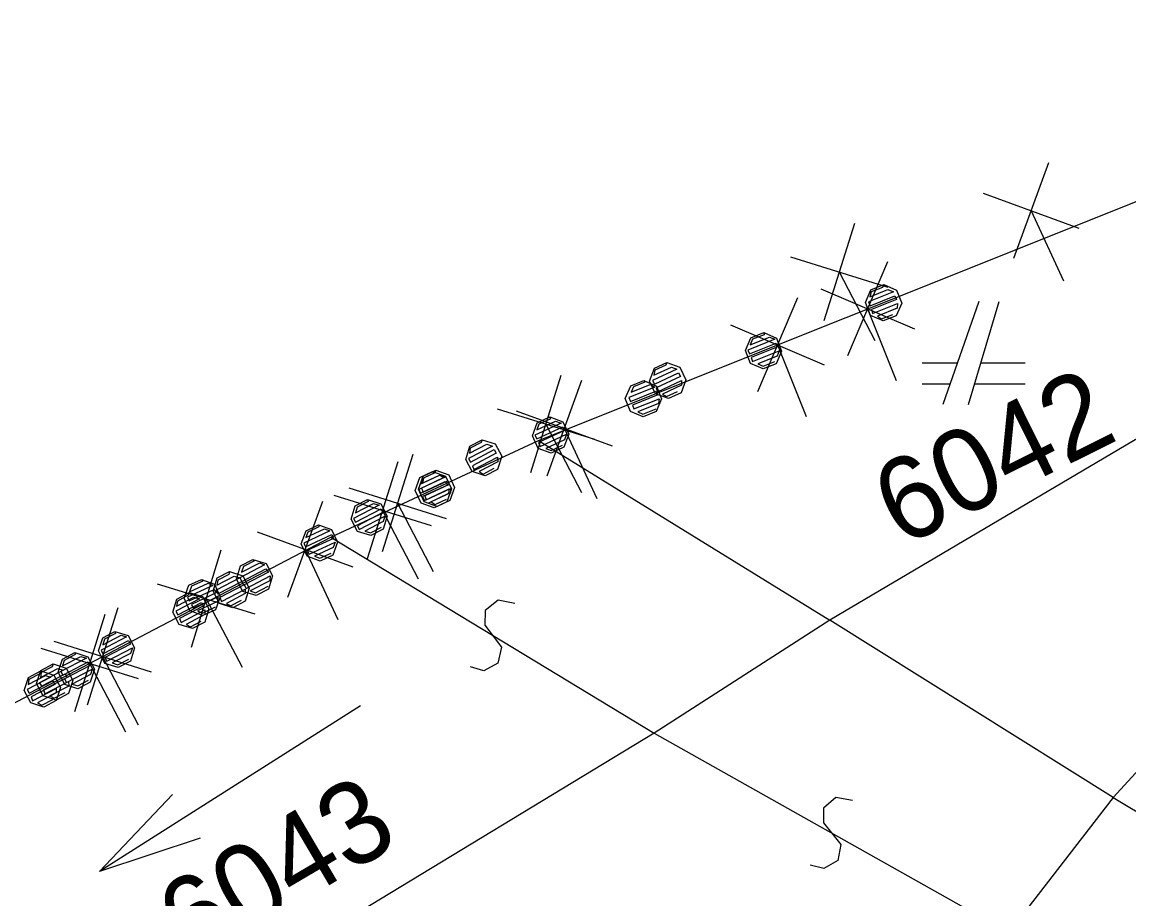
# Model space of a CAD drawing. Extents: x -266179 to -264727, y -1243225 to -1241702.
# Drawn here: x -265619.79 to -265598.3, y -1241752.17 to -1241735.15 of the extents above; entities that cross this region are included whole.
import ezdxf

# ---------------------------------------------------------------- set-up
doc = ezdxf.new("R2010")
doc.units = 0
for name, color, linetype in [('Vrstva 1', 7, 'Continuous'), ('Vrstva 19', 7, 'Continuous'), ('Vrstva 2', 7, 'Continuous'), ('Vrstva 21', 7, 'Continuous')]:
    doc.layers.add(name, color=color, linetype=linetype)

msp = doc.modelspace()

# ---------------------------------------------------------------- linework, layer by layer
at = {"layer": 'Vrstva 1'}
for p, q in [((-265609.77, -1241743.27), (-265589.45, -1241735.15)), ((-265585.26, -1241735.62), (-265604.11, -1241746.76)), ((-265585.26, -1241735.62), (-265598.61, -1241750.2)), ((-265601.22, -1241740.57), (-265601.92, -1241742.57)), ((-265601.42, -1241742.57), (-265600.82, -1241740.57)), ((-265601.64, -1241741.77), (-265602.32, -1241741.77)), ((-265600.32, -1241741.77), (-265601.18, -1241741.77)), ((-265602.32, -1241742.17), (-265601.78, -1241742.17)), ((-265601.3, -1241742.17), (-265600.32, -1241742.17)), ((-265613.8, -1241745.15), (-265609.77, -1241743.27)), ((-265609.77, -1241743.27), (-265604.11, -1241746.76)), ((-265617.23, -1241746.94), (-265613.8, -1241745.15)), ((-265604.11, -1241746.76), (-265607.52, -1241748.95)), ((-265598.61, -1241750.2), (-265604.11, -1241746.76)), ((-265622.91, -1241749.92), (-265617.23, -1241746.94)), ((-265613.227, -1241748.423), (-265618.293, -1241751.637)), ((-265607.52, -1241748.95), (-265618.34, -1241755.51)), ((-265598.61, -1241750.2), (-265600.64, -1241752.82)), ((-265598.61, -1241750.2), (-265594.43, -1241752.7))]:
    msp.add_line(p, q, dxfattribs=at)
msp.add_lwpolyline([(-265616.336, -1241750.988), (-265618.293, -1241751.637), (-265616.872, -1241750.144)], dxfattribs=at)
at = {"layer": 'Vrstva 19'}
for p, q in [((-265609.77, -1241743.27), (-265589.45, -1241735.15)), ((-265613.8, -1241745.15), (-265609.77, -1241743.27)), ((-265617.23, -1241746.94), (-265613.8, -1241745.15)), ((-265622.91, -1241749.92), (-265617.23, -1241746.94))]:
    msp.add_line(p, q, dxfattribs=at)
for points in [[(-265603.063, -1241740.246), (-265602.816, -1241740.352), (-265602.716, -1241740.603), (-265602.822, -1241740.849), (-265603.073, -1241740.95), (-265603.32, -1241740.844), (-265603.42, -1241740.593), (-265603.314, -1241740.346), (-265603.063, -1241740.246), (-265603.086, -1241740.298), (-265603.308, -1241740.387), (-265603.335, -1241740.483), (-265602.982, -1241740.342), (-265602.878, -1241740.387), (-265603.361, -1241740.58), (-265603.331, -1241740.654), (-265602.848, -1241740.461), (-265602.818, -1241740.536), (-265603.301, -1241740.729), (-265603.281, -1241740.807), (-265602.798, -1241740.614), (-265602.805, -1241740.703), (-265603.186, -1241740.855), (-265603.11, -1241740.911), (-265602.887, -1241740.822)], [(-265605.394, -1241741.177), (-265605.147, -1241741.283), (-265605.047, -1241741.534), (-265605.153, -1241741.78), (-265605.404, -1241741.881), (-265605.651, -1241741.775), (-265605.751, -1241741.524), (-265605.645, -1241741.277), (-265605.394, -1241741.177), (-265605.389, -1241741.218), (-265605.612, -1241741.307), (-265605.656, -1241741.411), (-265605.285, -1241741.262), (-265605.181, -1241741.307), (-265605.701, -1241741.515), (-265605.671, -1241741.589), (-265605.151, -1241741.381), (-265605.121, -1241741.456), (-265605.641, -1241741.663), (-265605.612, -1241741.738), (-265605.092, -1241741.53), (-265605.136, -1241741.634), (-265605.508, -1241741.782), (-265605.404, -1241741.827), (-265605.181, -1241741.738)], [(-265607.274, -1241741.754), (-265607.021, -1241741.846), (-265606.907, -1241742.091), (-265606.999, -1241742.343), (-265607.244, -1241742.457), (-265607.496, -1241742.365), (-265607.61, -1241742.12), (-265607.518, -1241741.868), (-265607.274, -1241741.754), (-265607.293, -1241741.807), (-265607.511, -1241741.908), (-265607.531, -1241742.006), (-265607.187, -1241741.846), (-265607.08, -1241741.884), (-265607.552, -1241742.104), (-265607.518, -1241742.177), (-265607.047, -1241741.957), (-265607.013, -1241742.029), (-265607.484, -1241742.249), (-265607.46, -1241742.326), (-265606.988, -1241742.106), (-265606.991, -1241742.196), (-265607.362, -1241742.369), (-265607.283, -1241742.42), (-265607.066, -1241742.319)], [(-265607.725, -1241742.108), (-265607.478, -1241742.214), (-265607.378, -1241742.465), (-265607.484, -1241742.711), (-265607.735, -1241742.812), (-265607.982, -1241742.706), (-265608.082, -1241742.455), (-265607.976, -1241742.208), (-265607.725, -1241742.108), (-265607.701, -1241742.141), (-265607.924, -1241742.23), (-265607.969, -1241742.334), (-265607.597, -1241742.186), (-265607.512, -1241742.238), (-265608.013, -1241742.438), (-265607.984, -1241742.513), (-265607.491, -1241742.316), (-265607.452, -1241742.387), (-265607.945, -1241742.583), (-265607.915, -1241742.657), (-265607.423, -1241742.461), (-265607.439, -1241742.554), (-265607.839, -1241742.713), (-265607.744, -1241742.761), (-265607.484, -1241742.658)], [(-265609.549, -1241742.814), (-265609.296, -1241742.906), (-265609.182, -1241743.151), (-265609.274, -1241743.403), (-265609.519, -1241743.517), (-265609.772, -1241743.425), (-265609.886, -1241743.18), (-265609.794, -1241742.928), (-265609.549, -1241742.814), (-265609.541, -1241742.854), (-265609.759, -1241742.956), (-265609.797, -1241743.062), (-265609.435, -1241742.893), (-265609.328, -1241742.932), (-265609.836, -1241743.168), (-265609.802, -1241743.241), (-265609.295, -1241743.004), (-265609.261, -1241743.077), (-265609.769, -1241743.313), (-265609.735, -1241743.386), (-265609.227, -1241743.149), (-265609.266, -1241743.256), (-265609.628, -1241743.425), (-265609.522, -1241743.463), (-265609.305, -1241743.362)], [(-265610.862, -1241743.256), (-265610.606, -1241743.336), (-265610.481, -1241743.576), (-265610.561, -1241743.832), (-265610.801, -1241743.957), (-265611.057, -1241743.876), (-265611.182, -1241743.637), (-265611.101, -1241743.381), (-265610.862, -1241743.256), (-265610.879, -1241743.31), (-265611.092, -1241743.421), (-265611.108, -1241743.519), (-265610.771, -1241743.344), (-265610.663, -1241743.378), (-265611.124, -1241743.618), (-265611.087, -1241743.689), (-265610.626, -1241743.448), (-265610.589, -1241743.519), (-265611.05, -1241743.76), (-265611.022, -1241743.836), (-265610.561, -1241743.595), (-265610.559, -1241743.684), (-265610.923, -1241743.874), (-265610.842, -1241743.922), (-265610.629, -1241743.811)], [(-265611.762, -1241743.848), (-265611.51, -1241743.94), (-265611.396, -1241744.185), (-265611.488, -1241744.437), (-265611.733, -1241744.551), (-265611.985, -1241744.459), (-265612.099, -1241744.214), (-265612.007, -1241743.962), (-265611.762, -1241743.848), (-265611.782, -1241743.901), (-265611.999, -1241744.002), (-265612.02, -1241744.1), (-265611.675, -1241743.94), (-265611.569, -1241743.978), (-265612.041, -1241744.198), (-265612.007, -1241744.271), (-265611.535, -1241744.051), (-265611.502, -1241744.123), (-265611.973, -1241744.343), (-265611.948, -1241744.42), (-265611.477, -1241744.2), (-265611.479, -1241744.29), (-265611.851, -1241744.463), (-265611.772, -1241744.514), (-265611.554, -1241744.413)], [(-265611.824, -1241743.874), (-265611.572, -1241743.966), (-265611.458, -1241744.211), (-265611.55, -1241744.463), (-265611.794, -1241744.577), (-265612.047, -1241744.485), (-265612.161, -1241744.24), (-265612.069, -1241743.988), (-265611.824, -1241743.874), (-265611.798, -1241743.906), (-265612.016, -1241744.007), (-265612.054, -1241744.114), (-265611.692, -1241743.945), (-265611.604, -1241743.992), (-265612.093, -1241744.22), (-265612.059, -1241744.292), (-265611.579, -1241744.069), (-265611.536, -1241744.137), (-265612.017, -1241744.361), (-265611.983, -1241744.433), (-265611.502, -1241744.209), (-265611.514, -1241744.303), (-265611.904, -1241744.485), (-265611.806, -1241744.528), (-265611.553, -1241744.409)], [(-265613.087, -1241744.417), (-265612.831, -1241744.498), (-265612.706, -1241744.737), (-265612.786, -1241744.993), (-265613.026, -1241745.118), (-265613.282, -1241745.038), (-265613.407, -1241744.798), (-265613.327, -1241744.542), (-265613.087, -1241744.417), (-265613.078, -1241744.457), (-265613.29, -1241744.568), (-265613.324, -1241744.676), (-265612.97, -1241744.491), (-265612.862, -1241744.525), (-265613.358, -1241744.784), (-265613.321, -1241744.855), (-265612.825, -1241744.596), (-265612.788, -1241744.667), (-265613.284, -1241744.926), (-265613.247, -1241744.997), (-265612.751, -1241744.738), (-265612.785, -1241744.846), (-265613.139, -1241745.031), (-265613.031, -1241745.065), (-265612.818, -1241744.954)], [(-265614.038, -1241744.908), (-265613.785, -1241745), (-265613.671, -1241745.245), (-265613.763, -1241745.497), (-265614.008, -1241745.611), (-265614.26, -1241745.519), (-265614.374, -1241745.274), (-265614.282, -1241745.022), (-265614.038, -1241744.908), (-265614.03, -1241744.948), (-265614.247, -1241745.05), (-265614.286, -1241745.156), (-265613.923, -1241744.987), (-265613.817, -1241745.026), (-265614.325, -1241745.262), (-265614.291, -1241745.335), (-265613.783, -1241745.098), (-265613.75, -1241745.171), (-265614.257, -1241745.407), (-265614.223, -1241745.48), (-265613.716, -1241745.243), (-265613.755, -1241745.35), (-265614.117, -1241745.519), (-265614.011, -1241745.557), (-265613.793, -1241745.456)], [(-265615.312, -1241745.578), (-265615.056, -1241745.659), (-265614.931, -1241745.898), (-265615.012, -1241746.155), (-265615.251, -1241746.28), (-265615.507, -1241746.199), (-265615.632, -1241745.96), (-265615.552, -1241745.703), (-265615.312, -1241745.578), (-265615.285, -1241745.609), (-265615.498, -1241745.72), (-265615.532, -1241745.828), (-265615.177, -1241745.643), (-265615.087, -1241745.686), (-265615.566, -1241745.936), (-265615.529, -1241746.007), (-265615.059, -1241745.762), (-265615.013, -1241745.828), (-265615.483, -1241746.073), (-265615.446, -1241746.144), (-265614.976, -1241745.899), (-265614.983, -1241745.993), (-265615.364, -1241746.192), (-265615.265, -1241746.231), (-265615.017, -1241746.101)], [(-265616.313, -1241745.968), (-265616.06, -1241746.06), (-265615.946, -1241746.305), (-265616.038, -1241746.557), (-265616.283, -1241746.671), (-265616.535, -1241746.579), (-265616.649, -1241746.334), (-265616.557, -1241746.082), (-265616.313, -1241745.968), (-265616.287, -1241746), (-265616.504, -1241746.101), (-265616.543, -1241746.208), (-265616.18, -1241746.039), (-265616.092, -1241746.086), (-265616.582, -1241746.314), (-265616.548, -1241746.386), (-265616.068, -1241746.162), (-265616.025, -1241746.231), (-265616.505, -1241746.455), (-265616.471, -1241746.527), (-265615.991, -1241746.303), (-265616.003, -1241746.397), (-265616.392, -1241746.579), (-265616.295, -1241746.621), (-265616.041, -1241746.503)], [(-265615.765, -1241745.815), (-265615.509, -1241745.895), (-265615.384, -1241746.135), (-265615.465, -1241746.391), (-265615.704, -1241746.516), (-265615.96, -1241746.435), (-265616.085, -1241746.196), (-265616.005, -1241745.94), (-265615.765, -1241745.815), (-265615.782, -1241745.869), (-265615.995, -1241745.98), (-265616.011, -1241746.078), (-265615.674, -1241745.903), (-265615.567, -1241745.937), (-265616.028, -1241746.177), (-265615.991, -1241746.248), (-265615.53, -1241746.007), (-265615.493, -1241746.078), (-265615.954, -1241746.319), (-265615.925, -1241746.394), (-265615.464, -1241746.154), (-265615.463, -1241746.243), (-265615.826, -1241746.433), (-265615.745, -1241746.481), (-265615.532, -1241746.37)], [(-265616.55, -1241746.222), (-265616.293, -1241746.302), (-265616.168, -1241746.541), (-265616.248, -1241746.798), (-265616.487, -1241746.923), (-265616.744, -1241746.843), (-265616.869, -1241746.604), (-265616.789, -1241746.348), (-265616.55, -1241746.222), (-265616.567, -1241746.276), (-265616.779, -1241746.388), (-265616.795, -1241746.486), (-265616.459, -1241746.31), (-265616.351, -1241746.344), (-265616.811, -1241746.585), (-265616.774, -1241746.656), (-265616.313, -1241746.415), (-265616.276, -1241746.485), (-265616.737, -1241746.727), (-265616.709, -1241746.802), (-265616.248, -1241746.561), (-265616.246, -1241746.65), (-265616.609, -1241746.841), (-265616.528, -1241746.888), (-265616.315, -1241746.777)], [(-265617.991, -1241746.976), (-265617.734, -1241747.057), (-265617.609, -1241747.296), (-265617.69, -1241747.552), (-265617.929, -1241747.677), (-265618.186, -1241747.597), (-265618.311, -1241747.357), (-265618.23, -1241747.101), (-265617.991, -1241746.976), (-265617.981, -1241747.016), (-265618.194, -1241747.127), (-265618.228, -1241747.235), (-265617.873, -1241747.05), (-265617.765, -1241747.084), (-265618.262, -1241747.343), (-265618.225, -1241747.414), (-265617.728, -1241747.155), (-265617.691, -1241747.226), (-265618.188, -1241747.485), (-265618.151, -1241747.556), (-265617.654, -1241747.297), (-265617.688, -1241747.405), (-265618.043, -1241747.59), (-265617.935, -1241747.624), (-265617.722, -1241747.513)], [(-265618.773, -1241747.388), (-265618.516, -1241747.468), (-265618.391, -1241747.707), (-265618.471, -1241747.964), (-265618.71, -1241748.089), (-265618.966, -1241748.009), (-265619.092, -1241747.77), (-265619.012, -1241747.513), (-265618.773, -1241747.388), (-265618.763, -1241747.428), (-265618.975, -1241747.54), (-265619.009, -1241747.648), (-265618.655, -1241747.462), (-265618.547, -1241747.495), (-265619.043, -1241747.756), (-265619.006, -1241747.826), (-265618.51, -1241747.566), (-265618.473, -1241747.637), (-265618.969, -1241747.897), (-265618.931, -1241747.968), (-265618.435, -1241747.708), (-265618.469, -1241747.816), (-265618.823, -1241748.002), (-265618.715, -1241748.035), (-265618.503, -1241747.924)], [(-265619.194, -1241747.609), (-265618.937, -1241747.689), (-265618.812, -1241747.929), (-265618.892, -1241748.185), (-265619.131, -1241748.31), (-265619.387, -1241748.23), (-265619.513, -1241747.991), (-265619.433, -1241747.735), (-265619.194, -1241747.609), (-265619.211, -1241747.663), (-265619.423, -1241747.775), (-265619.439, -1241747.874), (-265619.103, -1241747.697), (-265618.995, -1241747.731), (-265619.455, -1241747.972), (-265619.418, -1241748.043), (-265618.957, -1241747.802), (-265618.92, -1241747.873), (-265619.381, -1241748.114), (-265619.352, -1241748.19), (-265618.892, -1241747.948), (-265618.89, -1241748.037), (-265619.253, -1241748.228), (-265619.172, -1241748.275), (-265618.959, -1241748.164)], [(-265619.433, -1241747.744), (-265619.177, -1241747.824), (-265619.052, -1241748.064), (-265619.132, -1241748.32), (-265619.372, -1241748.445), (-265619.628, -1241748.364), (-265619.753, -1241748.125), (-265619.672, -1241747.869), (-265619.433, -1241747.744), (-265619.45, -1241747.798), (-265619.663, -1241747.909), (-265619.679, -1241748.007), (-265619.342, -1241747.832), (-265619.234, -1241747.866), (-265619.695, -1241748.106), (-265619.658, -1241748.177), (-265619.197, -1241747.936), (-265619.16, -1241748.007), (-265619.621, -1241748.248), (-265619.593, -1241748.323), (-265619.132, -1241748.083), (-265619.13, -1241748.172), (-265619.494, -1241748.362), (-265619.413, -1241748.41), (-265619.2, -1241748.299)]]:
    msp.add_lwpolyline(points, dxfattribs=at)
at = {"layer": 'Vrstva 2'}
for p, q in [((-265613.8, -1241745.15), (-265607.52, -1241748.95)), ((-265607.52, -1241748.95), (-265600.64, -1241752.82))]:
    msp.add_line(p, q, dxfattribs=at)
for points in [[(-265610.229, -1241746.434), (-265610.551, -1241746.368), (-265610.801, -1241746.568), (-265610.81, -1241746.854), (-265610.486, -1241747.284), (-265610.556, -1241747.592), (-265610.832, -1241747.74), (-265611.091, -1241747.666)], [(-265603.669, -1241750.256), (-265603.993, -1241750.2), (-265604.236, -1241750.407), (-265604.236, -1241750.694), (-265603.899, -1241751.113), (-265603.958, -1241751.424), (-265604.23, -1241751.581), (-265604.491, -1241751.514)]]:
    msp.add_lwpolyline(points, dxfattribs=at)
at = {"layer": 'Vrstva 21'}
for p, q in [((-265609.77, -1241743.27), (-265589.45, -1241735.15)), ((-265599.866, -1241737.881), (-265600.544, -1241739.741)), ((-265601.135, -1241738.472), (-265599.275, -1241739.15)), ((-265600.205, -1241738.811), (-265599.572, -1241740.17)), ((-265603.635, -1241739.056), (-265604.229, -1241740.945)), ((-265604.876, -1241739.703), (-265602.988, -1241740.297)), ((-265602.989, -1241739.806), (-265603.77, -1241741.625)), ((-265603.932, -1241740), (-265603.238, -1241741.33)), ((-265604.289, -1241740.325), (-265602.47, -1241741.106)), ((-265604.737, -1241740.504), (-265605.518, -1241742.324)), ((-265603.379, -1241740.715), (-265602.823, -1241742.108)), ((-265606.037, -1241741.023), (-265604.218, -1241741.804)), ((-265605.127, -1241741.414), (-265604.571, -1241742.807)), ((-265609.332, -1241742.007), (-265609.922, -1241743.897)), ((-265608.931, -1241742.104), (-265609.609, -1241743.964)), ((-265610.572, -1241742.657), (-265608.682, -1241743.247)), ((-265610.2, -1241742.695), (-265608.34, -1241743.373)), ((-265609.627, -1241742.952), (-265608.93, -1241744.28)), ((-265609.27, -1241743.034), (-265608.636, -1241744.394)), ((-265613.8, -1241745.15), (-265609.77, -1241743.27)), ((-265612.208, -1241743.541), (-265612.801, -1241745.43)), ((-265612.501, -1241743.682), (-265613.094, -1241745.571)), ((-265613.449, -1241744.189), (-265611.56, -1241744.782)), ((-265613.961, -1241744.456), (-265614.639, -1241746.316)), ((-265613.742, -1241744.33), (-265611.853, -1241744.923)), ((-265612.504, -1241744.486), (-265611.81, -1241745.816)), ((-265612.797, -1241744.627), (-265612.103, -1241745.957)), ((-265615.23, -1241745.047), (-265613.37, -1241745.725)), ((-265617.23, -1241746.94), (-265613.8, -1241745.15)), ((-265615.933, -1241745.397), (-265616.513, -1241747.29)), ((-265614.3, -1241745.386), (-265613.667, -1241746.746)), ((-265617.169, -1241746.053), (-265615.276, -1241746.634)), ((-265616.223, -1241746.344), (-265615.52, -1241747.668)), ((-265617.936, -1241746.519), (-265618.529, -1241748.408)), ((-265618.188, -1241746.651), (-265618.778, -1241748.541)), ((-265622.91, -1241749.92), (-265617.23, -1241746.94)), ((-265619.177, -1241747.167), (-265617.288, -1241747.76)), ((-265619.428, -1241747.301), (-265617.538, -1241747.891)), ((-265618.233, -1241747.463), (-265617.539, -1241748.793)), ((-265618.483, -1241747.596), (-265617.786, -1241748.925))]:
    msp.add_line(p, q, dxfattribs=at)

# ---------------------------------------------------------------- texts
at = {"layer": 'Vrstva 1'}
for s, rotation, p in [('6042', 26.4134, (-265602.725, -1241745.353)), ('6043', 30.4814, (-265616.523, -1241753.489))]:
    msp.add_text(s, height=1.6, rotation=rotation, dxfattribs=at).set_placement(p)

doc.saveas('drawing.dxf')
